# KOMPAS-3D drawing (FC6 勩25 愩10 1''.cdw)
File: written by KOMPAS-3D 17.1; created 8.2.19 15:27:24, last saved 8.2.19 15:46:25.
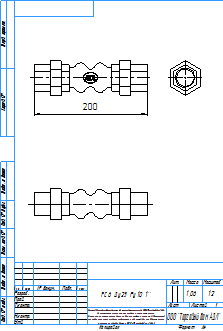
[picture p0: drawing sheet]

Sheet 1: A4, portrait

Title block, sheet 1: name: FC6 Ду25 Ру10 1''; mass: 1,06; sheets: 1; sheet format: A4; stored path: \\adlc.lan\data\АДЛ_ПКД\3D-модели\ADL production\Гибкие вставки серии FC\FC6\KOMPAS 2D\FC6 Ду25 Ру10 1''.cdw

Views: Вид 1
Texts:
  kka
  adl
  Рама для чертежей
  Лит-Масса-Масштаб
  Материал-Предприятие
  Масштаб
  Изм.
  Лист
  № докум.
  Подп.
  Дата
  Лит.
  Разраб.
  Пров.
  Т.контр.
  Листов
  Внимание! Данный продукт является объектом авторского права ООО «Торговый Дом АДЛ».
  Запрещается изменение, копирование, распространение
  (в том числе путем копирования на другие сайты и ресурсы в Интернете)
  или любое иное использование информации и объектов без предварительного
  согласия правообладателя (ООО «Торговый Дом АДЛ»).
  Н.контр.
  Утв.
  ООО "Торговый дом АДЛ"
  Изменение
  Номер документа
  Подпись
  Обозначение документа
  Наименование изделия
  Масса изделия по ГОСТ 2.109-73
  Порядковый номер листа
  Общее количество листов в документе
  Характер работы, выполненной лицом, подписавшим документ
  Наименование или индекс предприятия, выпускающего документ
  Инв. № подл.
  Подп. и дата
  Взам. инв. №
  Инв. № дубл.
  Инвентарный номер подлинника по ГОСТ 2.501-68
  Подпись принявшего подлинник в отдел технической документации
  Инвентарный номер подлинника, взамен которого выпущен данный подлинник
  Инвентарный номер дубликата по ГОСТ 2.502-68
  Подпись принявшего дубликат в отдел технической документации
  Справ. №
  Перв. примен.
  Обозначение документа, взамен или на основании которого выпущен данный документ
  Обозначение документа, в котором впервые записан данный документ
  Подпись лица, копировавшего чертеж
  Обозначение формата листа
  !Рама для чертежа
Dimensions and other numbers on the sheet: 200; 1:2; 1; 1,06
